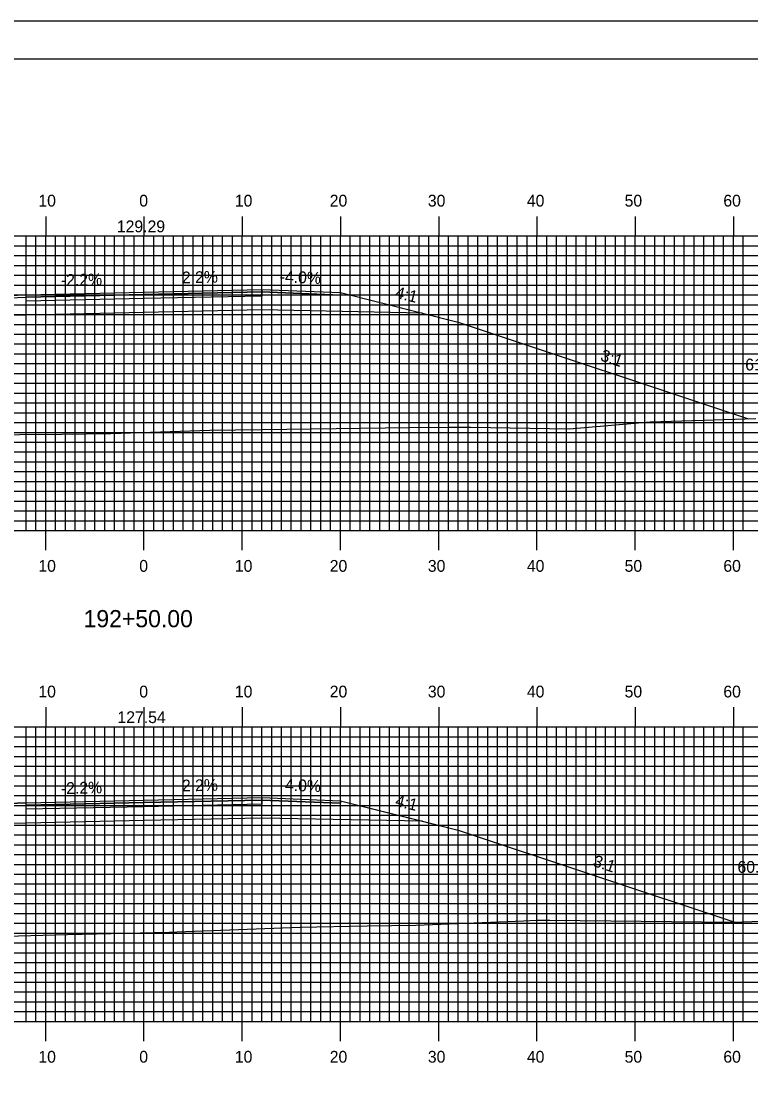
# Model space of a CAD drawing. Extents: x 1788550 to 1788893, y 442591 to 442811.
# Drawn here: x 1788703.1 to 1788777.4, y 442702.5 to 442810.5 of the extents above; entities that cross this region are included whole.
import ezdxf

# ---------------------------------------------------------------- set-up
doc = ezdxf.new("R2010")
doc.units = 0
for name, color, linetype in [('ANNOTATION', 7, 'Continuous'), ('BORDER', 7, 'Continuous'), ('D_Roadway_Centerline', 7, 'Continuous'), ('D_Roadway_Centerline_Text', 7, 'Continuous'), ('D_Roadway_Edge_Shoulder', 7, 'Continuous'), ('D_Roadway_Edge_TW', 7, 'Continuous'), ('D_Roadway_Pavement', 7, 'Continuous'), ('D_Roadway_SlopeLines', 7, 'Continuous'), ('D_Roadway_SubGrade', 7, 'Continuous'), ('D_Text_Standard', 7, 'Continuous'), ('H_V ANNOTATION', 7, 'Continuous'), ('MAJOR', 7, 'Continuous'), ('MINOR', 7, 'Continuous'), ('PLOT BOUNDARY', 7, 'Continuous'), ('S_Roadway_Centerline', 7, 'Continuous')]:
    doc.layers.add(name, color=color, linetype=linetype)

msp = doc.modelspace()

# ---------------------------------------------------------------- linework, layer by layer
at = {"layer": 'BORDER'}
msp.add_lwpolyline([(1788566.04, 442596.67), (1788886.04, 442596.67), (1788886.04, 442806.67), (1788566.04, 442806.67)], close=True, dxfattribs=at)
at = {"layer": 'D_Roadway_Centerline'}
for points in [[(1788648.65, 442767.71), (1788683.64, 442779.37), (1788687.28, 442780.28), (1788695.64, 442782.37), (1788703.64, 442782.69), (1788715.64, 442782.96), (1788727.64, 442783.22), (1788735.64, 442782.9), (1788744.01, 442780.81), (1788747.64, 442779.9), (1788777.18, 442770.05)], [(1788650.8, 442716.68), (1788683.64, 442727.62), (1788687.28, 442728.53), (1788695.64, 442730.62), (1788703.64, 442730.94), (1788715.64, 442731.21), (1788727.64, 442731.47), (1788735.64, 442731.15), (1788744.01, 442729.06), (1788747.64, 442728.15), (1788775.7, 442718.8)]]:
    msp.add_lwpolyline(points, dxfattribs=at)
at = {"layer": 'D_Roadway_Edge_Shoulder'}
for points in [[(1788703.64, 442782.69), (1788695.64, 442782.37), (1788695.64, 442782.12), (1788703.64, 442782.44)], [(1788727.64, 442783.22), (1788735.64, 442782.9), (1788735.64, 442782.65), (1788727.64, 442782.97)], [(1788703.64, 442730.94), (1788695.64, 442730.62), (1788695.64, 442730.37), (1788703.64, 442730.69)], [(1788727.64, 442731.47), (1788735.64, 442731.15), (1788735.64, 442730.9), (1788727.64, 442731.22)]]:
    msp.add_lwpolyline(points, close=True, dxfattribs=at)
at = {"layer": 'D_Roadway_Edge_TW'}
for points in [[(1788703.64, 442782.44), (1788703.64, 442782.69), (1788715.64, 442782.96), (1788727.64, 442783.22), (1788727.64, 442782.97), (1788715.64, 442782.71)], [(1788703.64, 442730.69), (1788703.64, 442730.94), (1788715.64, 442731.21), (1788727.64, 442731.47), (1788727.64, 442731.22), (1788715.64, 442730.96)]]:
    msp.add_lwpolyline(points, close=True, dxfattribs=at)
at = {"layer": 'D_Roadway_Pavement'}
for points in [[(1788703.64, 442782.03), (1788703.64, 442782.44), (1788715.64, 442782.71), (1788727.64, 442782.97), (1788727.64, 442782.55), (1788715.64, 442782.29)], [(1788703.64, 442730.28), (1788703.64, 442730.69), (1788715.64, 442730.96), (1788727.64, 442731.22), (1788727.64, 442730.8), (1788715.64, 442730.54)]]:
    msp.add_lwpolyline(points, close=True, dxfattribs=at)
at = {"layer": 'D_Roadway_SlopeLines'}
for points in [[(1788735.64, 442782.9), (1788747.64, 442779.9), (1788777.18, 442770.05)], [(1788735.64, 442731.15), (1788747.64, 442728.15), (1788775.7, 442718.8)]]:
    msp.add_lwpolyline(points, dxfattribs=at)
at = {"layer": 'D_Roadway_SubGrade'}
for points in [[(1788703.64, 442780.61), (1788687.28, 442780.28), (1788695.64, 442782.37), (1788695.64, 442782.12), (1788703.64, 442782.44), (1788715.64, 442782.71), (1788727.64, 442782.97), (1788735.64, 442782.65), (1788735.64, 442782.9), (1788744.01, 442780.81), (1788727.64, 442781.14), (1788715.64, 442780.87)], [(1788703.64, 442728.86), (1788687.28, 442728.53), (1788695.64, 442730.62), (1788695.64, 442730.37), (1788703.64, 442730.69), (1788715.64, 442730.96), (1788727.64, 442731.22), (1788735.64, 442730.9), (1788735.64, 442731.15), (1788744.01, 442729.06), (1788727.64, 442729.39), (1788715.64, 442729.12)]]:
    msp.add_lwpolyline(points, close=True, dxfattribs=at)
at = {"layer": 'MAJOR'}
for p, q in [((1788705.64, 442790.67), (1788705.64, 442788.67)), ((1788715.64, 442790.67), (1788715.64, 442788.67)), ((1788725.64, 442790.67), (1788725.64, 442788.67)), ((1788735.64, 442790.67), (1788735.64, 442788.67)), ((1788745.64, 442790.67), (1788745.64, 442788.67)), ((1788755.64, 442790.67), (1788755.64, 442788.67)), ((1788765.64, 442790.67), (1788765.64, 442788.67)), ((1788775.64, 442790.67), (1788775.64, 442788.67)), ((1788575.64, 442788.67), (1788855.64, 442788.67)), ((1788575.64, 442788.67), (1788855.64, 442788.67)), ((1788705.64, 442758.67), (1788705.64, 442788.67)), ((1788715.64, 442758.67), (1788715.64, 442788.67)), ((1788725.64, 442758.67), (1788725.64, 442788.67)), ((1788735.64, 442758.67), (1788735.64, 442788.67)), ((1788745.64, 442758.67), (1788745.64, 442788.67)), ((1788755.64, 442758.67), (1788755.64, 442788.67)), ((1788765.64, 442758.67), (1788765.64, 442788.67)), ((1788775.64, 442758.67), (1788775.64, 442788.67)), ((1788575.64, 442783.67), (1788855.64, 442783.67)), ((1788575.64, 442778.67), (1788855.64, 442778.67)), ((1788575.64, 442773.67), (1788855.64, 442773.67)), ((1788575.64, 442768.67), (1788855.64, 442768.67)), ((1788575.64, 442763.67), (1788855.64, 442763.67)), ((1788575.64, 442758.67), (1788855.64, 442758.67)), ((1788575.64, 442758.67), (1788855.64, 442758.67)), ((1788705.64, 442756.66), (1788705.64, 442758.67)), ((1788715.64, 442756.66), (1788715.64, 442758.67)), ((1788725.64, 442756.66), (1788725.64, 442758.67)), ((1788735.64, 442756.66), (1788735.64, 442758.67)), ((1788745.64, 442756.66), (1788745.64, 442758.67)), ((1788755.64, 442756.66), (1788755.64, 442758.67)), ((1788765.64, 442756.66), (1788765.64, 442758.67)), ((1788775.64, 442756.66), (1788775.64, 442758.67)), ((1788705.64, 442740.67), (1788705.64, 442738.67)), ((1788715.64, 442740.67), (1788715.64, 442738.67)), ((1788725.64, 442740.67), (1788725.64, 442738.67)), ((1788735.64, 442740.67), (1788735.64, 442738.67)), ((1788745.64, 442740.67), (1788745.64, 442738.67)), ((1788755.64, 442740.67), (1788755.64, 442738.67)), ((1788765.64, 442740.67), (1788765.64, 442738.67)), ((1788775.64, 442740.67), (1788775.64, 442738.67)), ((1788575.64, 442738.67), (1788855.64, 442738.67)), ((1788575.64, 442738.67), (1788855.64, 442738.67)), ((1788705.64, 442708.67), (1788705.64, 442738.67)), ((1788715.64, 442708.67), (1788715.64, 442738.67)), ((1788725.64, 442708.67), (1788725.64, 442738.67)), ((1788735.64, 442708.67), (1788735.64, 442738.67)), ((1788745.64, 442708.67), (1788745.64, 442738.67)), ((1788755.64, 442708.67), (1788755.64, 442738.67)), ((1788765.64, 442708.67), (1788765.64, 442738.67)), ((1788775.64, 442708.67), (1788775.64, 442738.67)), ((1788575.64, 442733.67), (1788855.64, 442733.67)), ((1788575.64, 442728.67), (1788855.64, 442728.67)), ((1788575.64, 442723.67), (1788855.64, 442723.67)), ((1788575.64, 442718.67), (1788855.64, 442718.67)), ((1788575.64, 442713.67), (1788855.64, 442713.67)), ((1788575.64, 442708.67), (1788855.64, 442708.67)), ((1788575.64, 442708.67), (1788855.64, 442708.67)), ((1788705.64, 442706.66), (1788705.64, 442708.67)), ((1788715.64, 442706.66), (1788715.64, 442708.67)), ((1788725.64, 442706.66), (1788725.64, 442708.67)), ((1788735.64, 442706.66), (1788735.64, 442708.67)), ((1788745.64, 442706.66), (1788745.64, 442708.67)), ((1788755.64, 442706.66), (1788755.64, 442708.67)), ((1788765.64, 442706.66), (1788765.64, 442708.67)), ((1788775.64, 442706.66), (1788775.64, 442708.67))]:
    msp.add_line(p, q, dxfattribs=at)
at = {"layer": 'MINOR'}
for p, q in [((1788703.64, 442758.67), (1788703.64, 442788.67)), ((1788704.64, 442758.67), (1788704.64, 442788.67)), ((1788706.64, 442758.67), (1788706.64, 442788.67)), ((1788707.64, 442758.67), (1788707.64, 442788.67)), ((1788708.64, 442758.67), (1788708.64, 442788.67)), ((1788709.64, 442758.67), (1788709.64, 442788.67)), ((1788710.64, 442758.67), (1788710.64, 442788.67)), ((1788711.64, 442758.67), (1788711.64, 442788.67)), ((1788712.64, 442758.67), (1788712.64, 442788.67)), ((1788713.64, 442758.67), (1788713.64, 442788.67)), ((1788714.64, 442758.67), (1788714.64, 442788.67)), ((1788716.64, 442758.67), (1788716.64, 442788.67)), ((1788717.64, 442758.67), (1788717.64, 442788.67)), ((1788718.64, 442758.67), (1788718.64, 442788.67)), ((1788719.64, 442758.67), (1788719.64, 442788.67)), ((1788720.64, 442758.67), (1788720.64, 442788.67)), ((1788721.64, 442758.67), (1788721.64, 442788.67)), ((1788722.64, 442758.67), (1788722.64, 442788.67)), ((1788723.64, 442758.67), (1788723.64, 442788.67)), ((1788724.64, 442758.67), (1788724.64, 442788.67)), ((1788726.64, 442758.67), (1788726.64, 442788.67)), ((1788727.64, 442758.67), (1788727.64, 442788.67)), ((1788728.64, 442758.67), (1788728.64, 442788.67)), ((1788729.64, 442758.67), (1788729.64, 442788.67)), ((1788730.64, 442758.67), (1788730.64, 442788.67)), ((1788731.64, 442758.67), (1788731.64, 442788.67)), ((1788732.64, 442758.67), (1788732.64, 442788.67)), ((1788733.64, 442758.67), (1788733.64, 442788.67)), ((1788734.64, 442758.67), (1788734.64, 442788.67)), ((1788736.64, 442758.67), (1788736.64, 442788.67)), ((1788737.64, 442758.67), (1788737.64, 442788.67)), ((1788738.64, 442758.67), (1788738.64, 442788.67)), ((1788739.64, 442758.67), (1788739.64, 442788.67)), ((1788740.64, 442758.67), (1788740.64, 442788.67)), ((1788741.64, 442758.67), (1788741.64, 442788.67)), ((1788742.64, 442758.67), (1788742.64, 442788.67)), ((1788743.64, 442758.67), (1788743.64, 442788.67)), ((1788744.64, 442758.67), (1788744.64, 442788.67)), ((1788746.64, 442758.67), (1788746.64, 442788.67)), ((1788747.64, 442758.67), (1788747.64, 442788.67)), ((1788748.64, 442758.67), (1788748.64, 442788.67)), ((1788749.64, 442758.67), (1788749.64, 442788.67)), ((1788750.64, 442758.67), (1788750.64, 442788.67)), ((1788751.64, 442758.67), (1788751.64, 442788.67)), ((1788752.64, 442758.67), (1788752.64, 442788.67)), ((1788753.64, 442758.67), (1788753.64, 442788.67)), ((1788754.64, 442758.67), (1788754.64, 442788.67)), ((1788756.64, 442758.67), (1788756.64, 442788.67)), ((1788757.64, 442758.67), (1788757.64, 442788.67)), ((1788758.64, 442758.67), (1788758.64, 442788.67)), ((1788759.64, 442758.67), (1788759.64, 442788.67)), ((1788760.64, 442758.67), (1788760.64, 442788.67)), ((1788761.64, 442758.67), (1788761.64, 442788.67)), ((1788762.64, 442758.67), (1788762.64, 442788.67)), ((1788763.64, 442758.67), (1788763.64, 442788.67)), ((1788764.64, 442758.67), (1788764.64, 442788.67)), ((1788766.64, 442758.67), (1788766.64, 442788.67)), ((1788767.64, 442758.67), (1788767.64, 442788.67)), ((1788768.64, 442758.67), (1788768.64, 442788.67)), ((1788769.64, 442758.67), (1788769.64, 442788.67)), ((1788770.64, 442758.67), (1788770.64, 442788.67)), ((1788771.64, 442758.67), (1788771.64, 442788.67)), ((1788772.64, 442758.67), (1788772.64, 442788.67)), ((1788773.64, 442758.67), (1788773.64, 442788.67)), ((1788774.64, 442758.67), (1788774.64, 442788.67)), ((1788776.64, 442758.67), (1788776.64, 442788.67)), ((1788575.64, 442787.67), (1788855.64, 442787.67)), ((1788575.64, 442786.67), (1788855.64, 442786.67)), ((1788575.64, 442785.67), (1788855.64, 442785.67)), ((1788575.64, 442784.67), (1788855.64, 442784.67)), ((1788575.64, 442782.67), (1788855.64, 442782.67)), ((1788575.64, 442781.67), (1788855.64, 442781.67)), ((1788575.64, 442780.67), (1788855.64, 442780.67)), ((1788575.64, 442779.67), (1788855.64, 442779.67)), ((1788575.64, 442777.67), (1788855.64, 442777.67)), ((1788575.64, 442776.67), (1788855.64, 442776.67)), ((1788575.64, 442775.67), (1788855.64, 442775.67)), ((1788575.64, 442774.67), (1788855.64, 442774.67)), ((1788575.64, 442772.67), (1788855.64, 442772.67)), ((1788575.64, 442771.67), (1788855.64, 442771.67)), ((1788575.64, 442770.67), (1788855.64, 442770.67)), ((1788575.64, 442769.67), (1788855.64, 442769.67)), ((1788575.64, 442767.67), (1788855.64, 442767.67)), ((1788575.64, 442766.67), (1788855.64, 442766.67)), ((1788575.64, 442765.67), (1788855.64, 442765.67)), ((1788575.64, 442764.67), (1788855.64, 442764.67)), ((1788575.64, 442762.67), (1788855.64, 442762.67)), ((1788575.64, 442761.67), (1788855.64, 442761.67)), ((1788575.64, 442760.67), (1788855.64, 442760.67)), ((1788575.64, 442759.67), (1788855.64, 442759.67)), ((1788703.64, 442708.67), (1788703.64, 442738.67)), ((1788704.64, 442708.67), (1788704.64, 442738.67)), ((1788706.64, 442708.67), (1788706.64, 442738.67)), ((1788707.64, 442708.67), (1788707.64, 442738.67)), ((1788708.64, 442708.67), (1788708.64, 442738.67)), ((1788709.64, 442708.67), (1788709.64, 442738.67)), ((1788710.64, 442708.67), (1788710.64, 442738.67)), ((1788711.64, 442708.67), (1788711.64, 442738.67)), ((1788712.64, 442708.67), (1788712.64, 442738.67)), ((1788713.64, 442708.67), (1788713.64, 442738.67)), ((1788714.64, 442708.67), (1788714.64, 442738.67)), ((1788716.64, 442708.67), (1788716.64, 442738.67)), ((1788717.64, 442708.67), (1788717.64, 442738.67)), ((1788718.64, 442708.67), (1788718.64, 442738.67)), ((1788719.64, 442708.67), (1788719.64, 442738.67)), ((1788720.64, 442708.67), (1788720.64, 442738.67)), ((1788721.64, 442708.67), (1788721.64, 442738.67)), ((1788722.64, 442708.67), (1788722.64, 442738.67)), ((1788723.64, 442708.67), (1788723.64, 442738.67)), ((1788724.64, 442708.67), (1788724.64, 442738.67)), ((1788726.64, 442708.67), (1788726.64, 442738.67)), ((1788727.64, 442708.67), (1788727.64, 442738.67)), ((1788728.64, 442708.67), (1788728.64, 442738.67)), ((1788729.64, 442708.67), (1788729.64, 442738.67)), ((1788730.64, 442708.67), (1788730.64, 442738.67)), ((1788731.64, 442708.67), (1788731.64, 442738.67)), ((1788732.64, 442708.67), (1788732.64, 442738.67)), ((1788733.64, 442708.67), (1788733.64, 442738.67)), ((1788734.64, 442708.67), (1788734.64, 442738.67)), ((1788736.64, 442708.67), (1788736.64, 442738.67)), ((1788737.64, 442708.67), (1788737.64, 442738.67)), ((1788738.64, 442708.67), (1788738.64, 442738.67)), ((1788739.64, 442708.67), (1788739.64, 442738.67)), ((1788740.64, 442708.67), (1788740.64, 442738.67)), ((1788741.64, 442708.67), (1788741.64, 442738.67)), ((1788742.64, 442708.67), (1788742.64, 442738.67)), ((1788743.64, 442708.67), (1788743.64, 442738.67)), ((1788744.64, 442708.67), (1788744.64, 442738.67)), ((1788746.64, 442708.67), (1788746.64, 442738.67)), ((1788747.64, 442708.67), (1788747.64, 442738.67)), ((1788748.64, 442708.67), (1788748.64, 442738.67)), ((1788749.64, 442708.67), (1788749.64, 442738.67)), ((1788750.64, 442708.67), (1788750.64, 442738.67)), ((1788751.64, 442708.67), (1788751.64, 442738.67)), ((1788752.64, 442708.67), (1788752.64, 442738.67)), ((1788753.64, 442708.67), (1788753.64, 442738.67)), ((1788754.64, 442708.67), (1788754.64, 442738.67)), ((1788756.64, 442708.67), (1788756.64, 442738.67)), ((1788757.64, 442708.67), (1788757.64, 442738.67)), ((1788758.64, 442708.67), (1788758.64, 442738.67)), ((1788759.64, 442708.67), (1788759.64, 442738.67)), ((1788760.64, 442708.67), (1788760.64, 442738.67)), ((1788761.64, 442708.67), (1788761.64, 442738.67)), ((1788762.64, 442708.67), (1788762.64, 442738.67)), ((1788763.64, 442708.67), (1788763.64, 442738.67)), ((1788764.64, 442708.67), (1788764.64, 442738.67)), ((1788766.64, 442708.67), (1788766.64, 442738.67)), ((1788767.64, 442708.67), (1788767.64, 442738.67)), ((1788768.64, 442708.67), (1788768.64, 442738.67)), ((1788769.64, 442708.67), (1788769.64, 442738.67)), ((1788770.64, 442708.67), (1788770.64, 442738.67)), ((1788771.64, 442708.67), (1788771.64, 442738.67)), ((1788772.64, 442708.67), (1788772.64, 442738.67)), ((1788773.64, 442708.67), (1788773.64, 442738.67)), ((1788774.64, 442708.67), (1788774.64, 442738.67)), ((1788776.64, 442708.67), (1788776.64, 442738.67)), ((1788575.64, 442737.67), (1788855.64, 442737.67)), ((1788575.64, 442736.67), (1788855.64, 442736.67)), ((1788575.64, 442735.67), (1788855.64, 442735.67)), ((1788575.64, 442734.67), (1788855.64, 442734.67)), ((1788575.64, 442732.67), (1788855.64, 442732.67)), ((1788575.64, 442731.67), (1788855.64, 442731.67)), ((1788575.64, 442730.67), (1788855.64, 442730.67)), ((1788575.64, 442729.67), (1788855.64, 442729.67)), ((1788575.64, 442727.67), (1788855.64, 442727.67)), ((1788575.64, 442726.67), (1788855.64, 442726.67)), ((1788575.64, 442725.67), (1788855.64, 442725.67)), ((1788575.64, 442724.67), (1788855.64, 442724.67)), ((1788575.64, 442722.67), (1788855.64, 442722.67)), ((1788575.64, 442721.67), (1788855.64, 442721.67)), ((1788575.64, 442720.67), (1788855.64, 442720.67)), ((1788575.64, 442719.67), (1788855.64, 442719.67)), ((1788575.64, 442717.67), (1788855.64, 442717.67)), ((1788575.64, 442716.67), (1788855.64, 442716.67)), ((1788575.64, 442715.67), (1788855.64, 442715.67)), ((1788575.64, 442714.67), (1788855.64, 442714.67)), ((1788575.64, 442712.67), (1788855.64, 442712.67)), ((1788575.64, 442711.67), (1788855.64, 442711.67)), ((1788575.64, 442710.67), (1788855.64, 442710.67)), ((1788575.64, 442709.67), (1788855.64, 442709.67))]:
    msp.add_line(p, q, dxfattribs=at)
at = {"layer": 'PLOT BOUNDARY'}
msp.add_lwpolyline([(1788549.86, 442590.55), (1788889.86, 442590.55), (1788889.86, 442810.55), (1788549.86, 442810.55)], close=True, dxfattribs=at)
at = {"layer": 'S_Roadway_Centerline'}
for points in [[(1788642.05, 442767.65), (1788656.06, 442767.78), (1788673.18, 442767.74), (1788674.07, 442767.74), (1788674.48, 442767.75), (1788685.66, 442768.33), (1788707.29, 442768.47), (1788712.28, 442768.56), (1788722.36, 442768.91), (1788730.17, 442769), (1788742.69, 442769.18), (1788746.62, 442769.2), (1788748.9, 442769.21), (1788758.93, 442769.02), (1788767.17, 442769.73), (1788777.92, 442770.08)], [(1788634.38, 442716.37), (1788646.55, 442716.72), (1788647.07, 442716.73), (1788647.99, 442716.72), (1788659.01, 442716.55), (1788680.79, 442716.78), (1788681.7, 442716.78), (1788682.22, 442716.84), (1788694.54, 442717.42), (1788701.6, 442717.37), (1788707.85, 442717.51), (1788718.22, 442717.76), (1788718.97, 442717.78), (1788731.54, 442718.28), (1788738.36, 442718.41), (1788743.31, 442718.47), (1788754.29, 442718.93), (1788755.61, 442718.98), (1788756.19, 442718.99), (1788756.94, 442718.99), (1788775.56, 442718.79), (1788791.23, 442719.32)]]:
    msp.add_lwpolyline(points, dxfattribs=at)

# ---------------------------------------------------------------- texts
at = {"layer": 'ANNOTATION'}
for s, rotation, p in [('-2.2%', 1.2603, (1788707.2, 442783.57)), ('2.2%', 1.2603, (1788719.52, 442783.84)), ('-4.0%', 357.7094, (1788729.44, 442783.95)), ('4:1', 345.9638, (1788741.15, 442782.39)), ('3:1', 341.5652, (1788762.02, 442776.02)), ('-2.2%', 1.2603, (1788707.2, 442731.82)), ('2.2%', 1.2603, (1788719.52, 442732.09)), ('-4.0%', 357.7094, (1788729.44, 442732.2)), ('4:1', 345.9638, (1788741.15, 442730.64)), ('3:1', 341.5652, (1788761.28, 442724.52))]:
    msp.add_text(s, height=1.2, rotation=rotation, dxfattribs=at).set_placement(p)
at = {"layer": 'D_Roadway_Centerline'}
for s, p in [('C', (1788715.64, 442782.96)), ('L', (1788715.64, 442782.95)), ('C', (1788715.64, 442731.21)), ('L', (1788715.64, 442731.2))]:
    msp.add_text(s, height=0.0146, dxfattribs=at).set_placement(p)
at = {"layer": 'D_Roadway_Centerline_Text'}
for s, p in [('129.29', (1788712.88, 442789.05)), ('127.54', (1788712.94, 442739.06))]:
    msp.add_text(s, height=1.2, dxfattribs=at).set_placement(p)
at = {"layer": 'D_Text_Standard'}
for s, p in [("61.5'", (1788776.85, 442774.98)), ("60.1'", (1788776.06, 442723.81))]:
    msp.add_text(s, height=1.2, dxfattribs=at).set_placement(p)
at = {"layer": 'H_V ANNOTATION'}
for s, height, p in [('10', 1.2, (1788704.89, 442791.67)), ('0', 1.2, (1788715.16, 442791.67)), ('10', 1.2, (1788724.89, 442791.67)), ('20', 1.2, (1788734.55, 442791.67)), ('30', 1.2, (1788744.54, 442791.67)), ('40', 1.2, (1788754.62, 442791.67)), ('50', 1.2, (1788764.57, 442791.67)), ('60', 1.2, (1788774.62, 442791.67)), ('10', 1.2, (1788704.89, 442754.47)), ('0', 1.2, (1788715.16, 442754.47)), ('10', 1.2, (1788724.89, 442754.47)), ('20', 1.2, (1788734.55, 442754.47)), ('30', 1.2, (1788744.54, 442754.47)), ('40', 1.2, (1788754.62, 442754.47)), ('50', 1.2, (1788764.57, 442754.47)), ('60', 1.2, (1788774.62, 442754.47)), ('192+50.00', 1.75, (1788709.49, 442748.82)), ('10', 1.2, (1788704.89, 442741.67)), ('0', 1.2, (1788715.16, 442741.67)), ('10', 1.2, (1788724.89, 442741.67)), ('20', 1.2, (1788734.55, 442741.67)), ('30', 1.2, (1788744.54, 442741.67)), ('40', 1.2, (1788754.62, 442741.67)), ('50', 1.2, (1788764.57, 442741.67)), ('60', 1.2, (1788774.62, 442741.67)), ('10', 1.2, (1788704.89, 442704.47)), ('0', 1.2, (1788715.16, 442704.47)), ('10', 1.2, (1788724.89, 442704.47)), ('20', 1.2, (1788734.55, 442704.47)), ('30', 1.2, (1788744.54, 442704.47)), ('40', 1.2, (1788754.62, 442704.47)), ('50', 1.2, (1788764.57, 442704.47)), ('60', 1.2, (1788774.62, 442704.47))]:
    msp.add_text(s, height=height, dxfattribs=at).set_placement(p)

doc.saveas('drawing.dxf')
